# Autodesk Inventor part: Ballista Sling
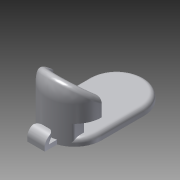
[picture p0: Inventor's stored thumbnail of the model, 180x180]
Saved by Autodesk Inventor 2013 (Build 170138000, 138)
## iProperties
Created: 2013-06
Part Number: Ballista Sling
Material: ABS Plastic
Document SubType Name: Modeling
Designer: merrill
Density: 1 g/cm^3
Author: merrill
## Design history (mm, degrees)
sketch "Sketch1"
  geometry: L1 (4.826, 0)-(-4.826, 0); L2 (-4.826, -12.7)-(4.826, -12.7); L3 (4.826, -12.7)-(4.826, 0); L4 (-4.826, -12.7)-(-4.826, 0); A1 r 4.826 centre (0, 0) between (4.826, 0) and (-4.826, 0); 2 further points
  constraints: 8 end point, 2 parallel, 2 point on circle, 2 tangent, 1 centre point, 1 coincident, 1 horizontal, 1 horizontal alignment, 1 midpoint, 1 perpendicular, 2 other
  dimensions: "d0" = 9.652 diameter of A1; "d4" = 12.7 distance of L2.start L1.end
extrude "Extrusion1" new body sketch "Sketch1" distance "d5" = 2.54; taper "d6" = 0 deg
sketch "Sketch2"
  geometry: L1 (4.826, 0)-(4.826, 12.7) reference; L2 (-8.255, 12.7)-(-8.255, 0); L3 (-8.255, 0)-(8.255, 0); L4 (8.255, 0)-(8.255, 12.7); L5 (8.255, 12.7)-(-8.255, 12.7); A1 r 4.826 centre (0, 0) between (-4.826, 0) and (4.826, 0) reference; A2 r 4.826 centre (0, 12.7) between (4.826, 12.7) and (-4.826, 12.7) reference; A3 r 8.255 centre (0, 12.7) between (-8.255, 12.7) and (8.255, 12.7); A4 r 8.255 centre (0, 0) between (-8.255, 0) and (8.255, 0)
  constraints: 8 end point, 5 point on circle, 2 centre point, 2 coincident, 2 perpendicular, 2 tangent, 1 parallel
  dimensions: "d7" = 16.51 diameter of A3; "d9" = 16.51 diameter of A4
extrude "Extrusion2" join sketch "Sketch2" distance "d10" = 2.159; taper "d11" = 0 deg
fillet "Fillet1" dims "d12" = 3.175
sketch "Sketch3"
  geometry: L1 (-8.255, 12.7)-(-8.255, 0) reference; L2 (-8.255, 0)-(-6.35, 0); L3 (6.35, 0)-(8.255, 0); A1 r 8.255 centre (0, 0) between (-8.255, 0) and (8.255, 0) reference; A2 r 8.255 centre (0, 0) between (-8.255, 0) and (8.255, 0); A3 r 6.35 centre (0, 0) between (-6.35, 0) and (6.35, 0)
  constraints: 4 end point, 4 point on circle, 2 centre point, 2 coincident, 1 collinear, 1 perpendicular
  dimensions: "d14" = 6.35 radius of A3
extrude "Extrusion3" join sketch "Sketch3" distance "d16" = 8.89; taper "d17" = 0 deg
sketch "Sketch4"
  geometry: L1 (8.255, 0)-(6.35, 0) reference; L2 (-6.35, 0)-(-8.255, 0) reference; A1 r 6.35 centre (0, 0) between (-6.35, 0) and (6.35, 0) reference; A2 r 8.255 centre (0, 0) between (-8.255, 0) and (8.255, 0) reference
revolve "Revolution1" sketch "Sketch4" stored, may be unused: angle "d18" = 40 deg
sketch "Sketch6"
  geometry: L1 (-4.826, -12.7)-(-4.826, 0) reference; L2 (-2.636, 7.823)-(-2.636, 11.539); L3 (-2.636, 11.539)-(0, 11.539); L4 (0, 11.539)-(0, 8.255); L5 (0, 17.096)-(0, -1.5); L6 (2.636, 11.539)-(0, 11.539); L7 (2.636, 7.823)-(2.636, 11.539); A1 r 8.255 centre (0, 0) between (8.255, 0) and (-8.255, 0) reference; A2 r 4.826 centre (0, 0) between (4.826, 0) and (-4.826, 0) reference; A3 r 8.255 centre (0, 0) between (0, 8.255) and (-2.636, 7.823); A4 r 8.255 centre (0, 0) between (2.636, 7.823) and (0, 8.255)
  constraints: 12 end point, 5 point on circle, 2 centre point, 2 parallel, 2 symmetric about line, 1 coincident, 1 collinear, 1 perpendicular, 1 other
extrude "Extrusion4" join sketch "Sketch6" distance "d23" = 1.27; taper "d24" = 0 deg
sketch "Sketch7"
  geometry: L1 (2.636, -11.539)-(2.636, -7.823) reference; L2 (-2.636, -11.539)-(2.636, -11.539); L3 (2.636, -11.539)-(2.636, -10.269); L4 (2.636, -10.269)-(-2.636, -10.269); L5 (-2.636, -10.269)-(-2.636, -11.539)
  constraints: 8 end point, 2 parallel, 1 horizontal, 1 perpendicular, 1 point on line
  dimensions: "d25" = 1.27 distance between parallel lines of L4 L2
sketch "Sketch8"
  geometry: L1 (3.718, 8.957)-(6.293, 8.943); L2 (3.718, 8.957)-(3.732, 11.532); L3 (6.293, 8.943)-(6.292, 8.635); A1 r 2.575 centre (3.718, 8.957) between (6.293, 8.943) and (3.732, 11.532); 1 further point
  constraints: 6 end point, 2 point on circle, 1 centre point, 1 tangent
  dimensions: "d27" = 90 deg angle of L1 L2
sweep "Sweep1" sketch "Sketch7", "Sketch8" dims "d28" = 0
chamfer "Chamfer1" distance "d29" = 1.016; stored, may be unused: second distance "d30" = 3.175, angle "d31" = 45 deg
fillet "Fillet6" dims "d32" = 1.397
sketch "Sketch9"
  geometry: L1 (9.694, 4.699)-(5.715, 4.699); L2 (5.715, 4.699)-(5.715, 8.509); L3 (5.715, 8.509)-(9.694, 8.509); L4 (9.694, 8.509)-(9.694, 4.699); L5 (13.46, 0)-(-14.122, 0) reference; L6 (0, -1.528)-(0, 14.89) reference; L7 (-9.694, 4.699)-(-5.715, 4.699); L8 (-5.715, 4.699)-(-5.715, 8.509); L9 (-5.715, 8.509)-(-9.694, 8.509); L10 (-9.694, 8.509)-(-9.694, 4.699); 1 further point
  constraints: 20 end point, 4 symmetric about line, 3 perpendicular, 2 horizontal, 2 parallel, 1 vertical
  dimensions: "d33" = 11.43 distance between parallel lines of L8 L2; "d35" = 3.81 distance between parallel lines of L3 L1; "d38" = 9.398 diameter of L1 L5
extrude "Extrusion5" cut sketch "Sketch9" distance "d36" = 7.62; taper "d37" = 0 deg
fillet "Fillet7" dims "d39" = 1.27
body "Solid1"
